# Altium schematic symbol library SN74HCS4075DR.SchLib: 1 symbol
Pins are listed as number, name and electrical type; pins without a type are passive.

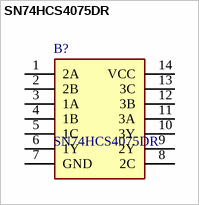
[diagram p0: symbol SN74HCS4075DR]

## SN74HCS4075DR
designator B?
Logic Gates 3-channel, 3-input OR gates with schmitt-trigger inputs; Manufacturer_Name: Texas Instruments; Geometry.Height: 1.75mm
footprint SOIC127P600X175-14N
pins: 1 2A, 2 2B, 3 1A, 4 1B, 5 1C, 6 1Y, 7 GND, 8 2C, 9 2Y, 10 3Y, 11 3A, 12 3B, 13 3C, 14 VCC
